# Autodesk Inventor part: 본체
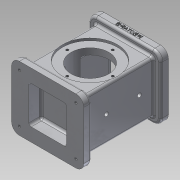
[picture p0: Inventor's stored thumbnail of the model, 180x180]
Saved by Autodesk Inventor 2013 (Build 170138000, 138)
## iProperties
Created: 2017-08
Part Number: 본체
Material: 알루미늄 6061
Document SubType Name: Modeling
Designer: Administrator
Density: 2.71 g/cm^3
Mass: 871.819 g
Surface Area: 642.819 cm^2
Volume: 321.704 cm^3
Author: Administrator
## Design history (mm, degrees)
sketch "스케치1"
  geometry: L1 (-36, 41)-(36, 41); L2 (46, 31)-(46, -31); L3 (36, -41)-(-36, -41); L4 (-46, -31)-(-46, 31); A1 r 10 centre (36, 31) between (46, 31) and (36, 41); A2 r 10 centre (-36, 31) between (-36, 41) and (-46, 31); A3 r 10 centre (-36, -31) between (-46, -31) and (-36, -41); A4 r 10 centre (36, -31) between (36, -41) and (46, -31); 6 further points
  constraints: 8 end point, 8 point on circle, 8 tangent, 6 point on line, 4 centre point, 3 equal radius, 2 midpoint, 2 parallel, 1 horizontal, 1 horizontal alignment, 1 perpendicular, 1 vertical alignment
  dimensions: "d0" = 92 distance of point (-46, 41) point (46, 41); "d2" = 82 distance of point (46, 41) point (46, -41); "d3" = 10 radius of A1
extrude "돌출1" new body sketch "스케치1" distance "d4" = 10; taper "d5" = 0 deg
sketch "스케치2"
  geometry: L1 (-36, 41)-(36, 41) reference; L2 (36, -41)-(-36, -41) reference; L3 (46, 31)-(46, -31) reference; L4 (-37, 0)-(-37, 30); L5 (-34, 33)-(34, 33); L6 (37, 30)-(37, -30); L7 (34, -33)-(-34, -33); L8 (-37, -30)-(-37, 0); A1 r 3 centre (-34, 30) between (-34, 33) and (-37, 30); A2 r 3 centre (34, 30) between (37, 30) and (34, 33); A3 r 3 centre (34, -30) between (34, -33) and (37, -30); A4 r 3 centre (-34, -30) between (-37, -30) and (-34, -33); 5 further points
  constraints: 10 end point, 8 point on circle, 8 point on line, 8 tangent, 4 centre point, 3 equal radius, 2 perpendicular, 1 parallel
  dimensions: "d11" = 33 distance of L4.start point (-37, 33); "d12" = 74 distance of point (-37, 33) point (37, 33); "d13" = 66 distance of point (37, 33) point (37, -33); "d14" = 74 distance of point (37, -33) point (-37, -33); "d15" = 33 distance of point (-37, -33) L4.start (derived); "d16" = 3 radius of A1; "d17" = 71 distance of L5.start point (37, 33); "d18" = 9 distance between parallel lines of L3 L6; "d19" = 74 distance between parallel lines of L2 L5
extrude "돌출2" join sketch "스케치2" distance "d20" = 88; taper "d21" = 0 deg
sketch "스케치3"
  geometry: L1 (-46, 0)-(-46, 31); L2 (-36, 41)-(36, 41); L3 (46, 31)-(46, -31); L4 (36, -41)-(-36, -41); L5 (-46, -31)-(-46, 0); A1 r 10 centre (-36, 31) between (-36, 41) and (-46, 31); A2 r 10 centre (36, 31) between (46, 31) and (36, 41); A3 r 10 centre (36, -31) between (36, -41) and (46, -31); A4 r 10 centre (-36, -31) between (-46, -31) and (-36, -41); 5 further points
  constraints: 10 end point, 9 tangent, 8 point on circle, 8 point on line, 4 centre point, 3 equal radius, 1 parallel
  dimensions: "d23" = 41 distance of L1.start point (-46, 41); "d24" = 92 distance of point (-46, 41) point (46, 41); "d25" = 82 distance of point (46, 41) point (46, -41); "d26" = 92 distance of point (46, -41) point (-46, -41); "d27" = 41 distance of point (-46, -41) L1.start (derived); "d28" = 10 radius of A1
extrude "돌출3" join sketch "스케치3" distance "d31" = 10; taper "d32" = 0 deg
sketch "스케치4"
  geometry: L1 (0, 0)-(68, 0) reference; C1 r 24 at (34, -44); 1 further point
  constraints: 1 centre point
  dimensions: "d34" = 48 diameter of C1; "d35" = 44 distance from line of C1.centre L1; "d36" = 55.60576 distance of L1.end C1.centre
extrude "돌출4" cut sketch "스케치4" distance "d37" = 68; taper "d38" = 0 deg
sketch "스케치5"
  geometry: C1 r 24 at (34, -44) reference; C2 r 35 at (34, -44); 1 further point
  constraints: 1 centre point, 1 coincident
  dimensions: "d39" = 70 diameter of C2
extrude "돌출5" cut sketch "스케치5" distance "d40" = 3; taper "d41" = 0 deg
sketch "스케치6"
  geometry: L1 (-46, 31)-(-46, -31) reference; L2 (46, -31)-(46, 31) reference; L3 (36, 41)-(-36, 41) reference; L4 (-24, 0)-(-24, 21); L5 (-21, 24)-(21, 24); L6 (24, 21)-(24, -21); L7 (21, -24)-(-21, -24); L8 (-24, -21)-(-24, 0); A1 r 3 centre (-21, 21) between (-21, 24) and (-24, 21); A2 r 3 centre (21, 21) between (24, 21) and (21, 24); A3 r 3 centre (21, -21) between (21, -24) and (24, -21); A4 r 3 centre (-21, -21) between (-24, -21) and (-21, -24); 5 further points
  constraints: 10 end point, 9 tangent, 8 point on circle, 8 point on line, 4 centre point, 3 equal radius, 2 parallel, 1 perpendicular
  dimensions: "d46" = 24 distance of L4.start point (-24, 24); "d47" = 48 distance of point (-24, 24) point (24, 24); "d48" = 48 distance of point (24, 24) point (24, -24); "d49" = 48 distance of point (24, -24) point (-24, -24); "d50" = 24 distance of point (-24, -24) L4.start (derived); "d51" = 3 radius of A1; "d52" = 65 distance between parallel lines of L3 L7; "d53" = 70 distance between parallel lines of L8 L2
extrude "돌출6" cut sketch "스케치6" distance "d54" = 16; taper "d55" = 0 deg
sketch "스케치7"
  geometry: L1 (-22, 0)-(-22, 19); L2 (-19, 22)-(19, 22); L3 (22, 19)-(22, -19); L4 (19, -22)-(-19, -22); L5 (-22, -19)-(-22, 0); A1 r 3 centre (-19, 19) between (-19, 22) and (-22, 19); A2 r 3 centre (19, 19) between (22, 19) and (19, 22); A3 r 3 centre (19, -19) between (19, -22) and (22, -19); A4 r 3 centre (-19, -19) between (-22, -19) and (-19, -22); 5 further points
  constraints: 10 end point, 8 point on circle, 8 point on line, 8 tangent, 4 centre point, 3 equal radius, 1 parallel
  dimensions: "d57" = 22 distance of L1.start point (-22, 22); "d58" = 44 distance of point (-22, 22) point (22, 22); "d59" = 44 distance of point (22, 22) point (22, -22); "d60" = 44 distance of point (22, -22) point (-22, -22); "d61" = 22 distance of point (-22, -22) L1.start (derived); "d62" = 3 radius of A1
extrude "돌출7" cut sketch "스케치7" distance "d63" = 82; taper "d64" = 0 deg
sketch "스케치8"
  geometry: L1 (-26.39, 0)-(-26.39, 26); L2 (-26.39, 26)-(25.61, 26); L3 (25.61, 26)-(25.61, -26); L4 (25.61, -26)-(-26.39, -26); L5 (-26.39, -26)-(-26.39, 0); 1 further point
  constraints: 10 end point, 1 perpendicular
  dimensions: "d67" = 26 distance of L1.start L1.end; "d68" = 52 distance of L1.end L2.end; "d69" = 52 distance of L2.end L3.end; "d70" = 52 distance of L3.end L4.end; "d71" = 26 distance of L4.end L1.start (derived)
extrude "돌출8" cut sketch "스케치8" distance "d72" = 8; taper "d73" = 0 deg
sketch "스케치9"
  geometry: 2 further points
hole "구멍1" sketch "스케치9" at (0, 29) diameter "d75" = 3.242; stored, may be unused: countersink angle "d79" = 90 deg, drill point angle "d81" = 118 deg; dims "d76" = 4, "d77" = 4, "d78" = 2, "d80" = 6
sketch "스케치10"
  geometry: 5 further points
hole "구멍2" sketch "스케치10" at (-36, 31), (36, 31), (36, -31), (-36, -31) diameter "d87" = 3.242; stored, may be unused: countersink angle "d91" = 90 deg, drill point angle "d93" = 118 deg; dims "d88" = 4, "d89" = 4, "d90" = 2, "d92" = 6
node "작업 평면1"
sketch "스케치11"
  geometry: C1 r 2.5 at (30, -18); C2 r 2.5 at (30, -60); 1 further point
  constraints: 2 centre point
  dimensions: "d99" = 5 diameter of C1; "d100" = 5 diameter of C2; "d101" = 18 distance of point (30, 0) C1.centre; "d102" = 60 distance of point (30, 0) C2.centre; "d103" = 42 distance of C1.centre C2.centre
extrude "돌출9" cut sketch "스케치11" stored distance "d104" = 8; taper "d105" = 0 deg
sketch "스케치13"
  geometry: 2 further points
  constraints: 1 other
feature "엠보싱1" sketch "스케치13" dims "d0" = 92, "d2" = 82, "d3" = 10, "d109" = 0.5, "d110" = 0
fillet "모깎기1" dims "d111" = 3
chamfer "모따기1" distance "d112" = 1; stored, may be unused: second distance "d113" = 2, angle "d114" = 45 deg
chamfer "모따기2" distance "d115" = 1; stored, may be unused: second distance "d116" = 2, angle "d117" = 45 deg
chamfer "모따기3" distance "d118" = 1; stored, may be unused: second distance "d119" = 2, angle "d120" = 45 deg
chamfer "모따기4" distance "d121" = 1; stored, may be unused: second distance "d122" = 2, angle "d123" = 45 deg
node "솔리드1"
mirror "대칭1"
pattern_circular "원형 패턴1" dims angle "d83" = 360 deg
mirror "대칭2"
mirror "대칭3"
other parameters: "d94" = -54
